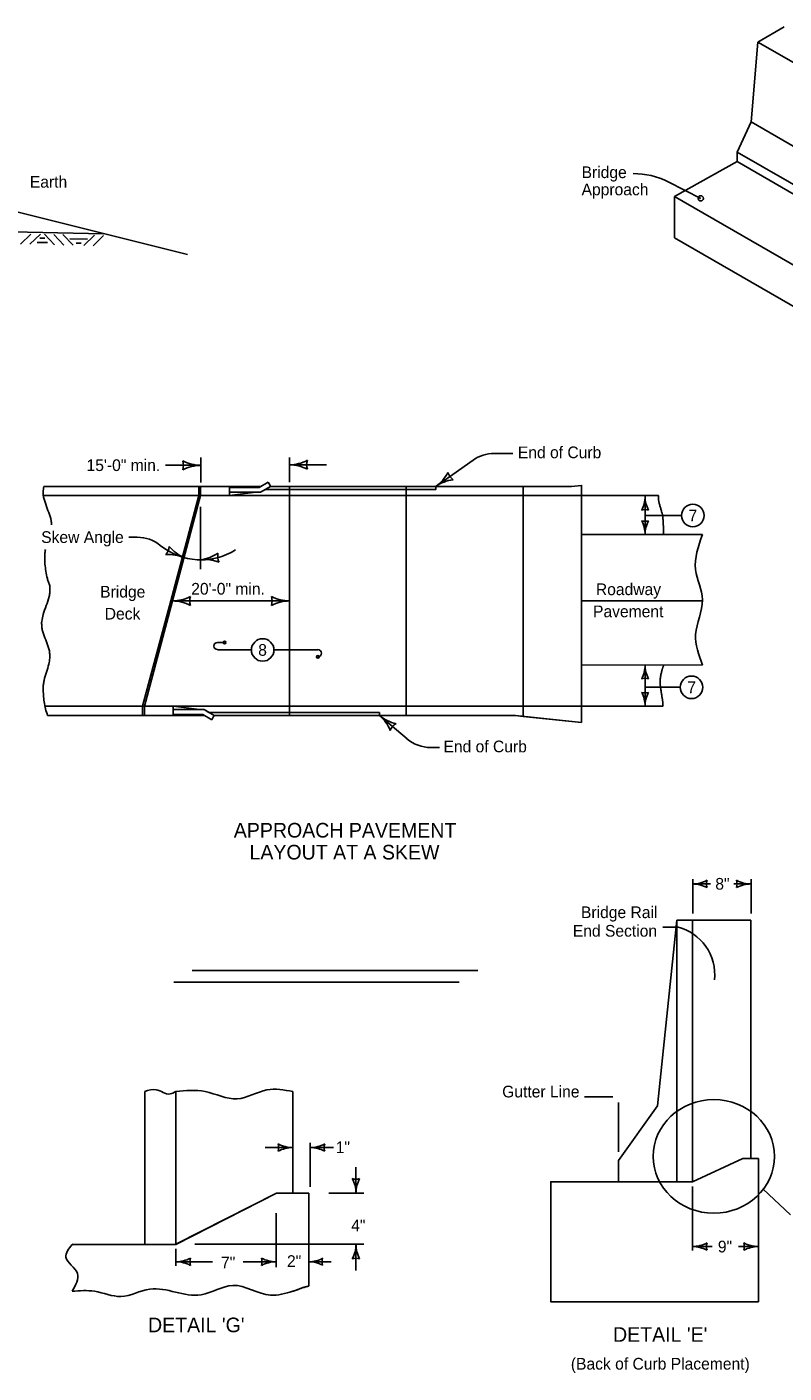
# Model space of a CAD drawing. Extents: x 9234 to 81668, y 5635 to 15999.
# Drawn here: x 18357 to 19394, y 12363 to 14204 of the extents above; entities that cross this region are included whole.
import ezdxf

# ---------------------------------------------------------------- set-up
doc = ezdxf.new("R2010")
doc.units = 0
for name, color, linetype in [('PC_REBAR', 7, 'Continuous'), ('PS_BOLT', 7, 'Continuous'), ('PS_CONST', 7, 'Continuous'), ('PS_DIM', 7, 'Continuous')]:
    doc.layers.add(name, color=color, linetype=linetype)

msp = doc.modelspace()

# ---------------------------------------------------------------- linework, layer by layer
at = {"layer": 'PC_REBAR'}
msp.add_circle((19279.6, 13969.9), 3.54, dxfattribs=at)
at = {"layer": 'PS_CONST'}
for centre in [(18627.7, 13362.4), (18755.4, 13342.7)]:
    msp.add_circle(centre, 1.78, dxfattribs=at)
for centre, radius, start, end in [((19268.2, 13074.5), 42.5, 270, 298.0725), ((19268.2, 12989.5), 42.5, 61.9275, 90), ((19303.8, 13032), 16.4, 162.2666, 197.7334), ((19312.8, 13032), 16.4, 342.2666, 17.7333), ((19348.5, 13074.5), 42.5, 241.9275, 270), ((19348.5, 12989.5), 42.5, 90, 118.0725), ((18685.3, 12671.4), 16.4, 342.2666, 17.7333), ((18721, 12713.9), 42.5, 241.9275, 270), ((18721, 12628.9), 42.5, 90, 118.0725), ((18744.8, 12713.9), 42.5, 270, 298.0725), ((18744.8, 12628.9), 42.5, 61.9275, 90), ((18780.4, 12671.4), 16.4, 162.2666, 197.7334), ((18807.5, 12644.6), 16.4, 252.2666, 287.7333), ((18765, 12609), 42.5, 360, 28.0725), ((18850, 12609), 42.5, 151.9275, 180), ((19268.2, 12578.5), 42.5, 270, 298.0725), ((19303.8, 12536), 16.4, 162.2666, 197.7334), ((19322.8, 12536), 16.4, 342.2666, 17.7333), ((19358.5, 12578.5), 42.5, 241.9275, 270), ((18765, 12539.1), 42.5, 331.9275, 360), ((18850, 12539.1), 42.5, 180, 208.0725), ((19268.2, 12493.5), 42.5, 61.9275, 90), ((19358.5, 12493.5), 42.5, 90, 118.0725), ((18561, 12557.7), 42.5, 270, 298.0725), ((18561, 12472.7), 42.5, 61.9275, 90), ((18596.6, 12515.2), 16.4, 162.2666, 197.7334), ((18662.4, 12515.2), 16.4, 342.2666, 17.7333), ((18698.1, 12557.7), 42.5, 241.9275, 270), ((18698.1, 12472.7), 42.5, 90, 118.0725), ((18807.5, 12503.5), 16.4, 72.2666, 107.7334)]:
    msp.add_arc(centre, radius, start, end, dxfattribs=at)
at = {"layer": 'PS_DIM'}
for p, q in [((19542.8, 14076.9), (19357.8, 14183.7)), ((19533.4, 13967.8), (19348.4, 14074.6)), ((19514.5, 13926.4), (19329.5, 14033.2)), ((19329.5, 14033.2), (19329.5, 14020.1)), ((19234.9, 13992.4), (19258.2, 13980.6)), ((19258.2, 13980.6), (19279.6, 13969.9)), ((18328.6, 13955), (18576.8, 13892.9)), ((18284.3, 13925.1), (18462.2, 13921.5)), ((18362.6, 13920.9), (18348.1, 13907)), ((18375.6, 13920.8), (18361.2, 13907)), ((18381, 13920.7), (18394.8, 13906.3)), ((18394, 13920.3), (18407.8, 13905.8)), ((18406.4, 13920.2), (18420.3, 13905.8)), ((18449.7, 13919.4), (18435.2, 13905.5)), ((18462.1, 13918.9), (18447.7, 13905)), ((18595, 13615.5), (18595, 13581.4)), ((18716.4, 13615.5), (18716.4, 13581.5)), ((18916.9, 13575.8), (18968, 13611.7)), ((18996.7, 13620.8), (19022.5, 13620.8)), ((18595, 13604.7), (18546.6, 13604.7)), ((18767.3, 13605.4), (18716.4, 13605.4)), ((18380.3, 13575.8), (18634.5, 13575.8)), ((18592.6, 13563.2), (18592.6, 13575.8)), ((18594.9, 13563.2), (18594.9, 13575.8)), ((18634.5, 13563.2), (18634.5, 13575.8)), ((18677.2, 13575.8), (18634.5, 13575.8)), ((18674.9, 13574.5), (18687.2, 13581.6)), ((18690.5, 13575.8), (18676.7, 13567.8)), ((18690.5, 13575.8), (18676.7, 13567.8)), ((18683.6, 13571.8), (18916.9, 13571.8)), ((18687.2, 13581.6), (18689.9, 13577)), ((18690.5, 13575.8), (18689.9, 13577)), ((18716.4, 13575.8), (18690.5, 13575.8)), ((18716.4, 13419.2), (18716.4, 13575.8)), ((18716.4, 13575.8), (18876.4, 13575.8)), ((18876.4, 13575.8), (18876.4, 13419.2)), ((18876.4, 13575.8), (19102.5, 13575.8)), ((18916.9, 13575.8), (18916.9, 13571.8)), ((19036.4, 13575.8), (19036.4, 13261.3)), ((19102.5, 13575.8), (19116.4, 13577.3)), ((19116.4, 13577.3), (19116.4, 13419.2)), ((18379.6, 13563.2), (18634.5, 13563.2)), ((18594.9, 13563.2), (18517.8, 13275.2)), ((18592.6, 13563.2), (18554, 13419.2)), ((18594.9, 13563.2), (18556.4, 13419.2)), ((18634.5, 13563.2), (18594.9, 13563.2)), ((18634.5, 13567.8), (18676.7, 13567.8)), ((18634.5, 13563.2), (18670.4, 13567.8)), ((18670.4, 13567.8), (18634.5, 13563.2)), ((19221.6, 13563.2), (18634.5, 13563.2)), ((18676.7, 13567.8), (18670.4, 13567.8)), ((19203.3, 13510), (19203.3, 13563.2)), ((18594.9, 13462.5), (18594.9, 13547.9)), ((19203.3, 13536), (19232.8, 13536)), ((19232.8, 13536), (19253.4, 13536)), ((18496.4, 13506.3), (18508.2, 13506.3)), ((19116.4, 13510), (19281.9, 13510)), ((18515.5, 13275.2), (18554, 13419.2)), ((18517.8, 13275.2), (18556.4, 13419.2)), ((18716.4, 13419.2), (18556.4, 13419.2)), ((18716.4, 13419.2), (18556.4, 13419.2)), ((18716.4, 13419.2), (18716.4, 13262.5)), ((18876.4, 13262.5), (18876.4, 13419.2)), ((19116.4, 13419.2), (19281.9, 13419.2)), ((19116.4, 13419.2), (19116.4, 13252.7)), ((18627.7, 13362.4), (18617.9, 13362.4)), ((18664.4, 13352.5), (18617.9, 13352.5)), ((18695.1, 13352.5), (18755.4, 13352.5)), ((19116.4, 13331.6), (19281.9, 13331.5)), ((19203.3, 13275.2), (19203.3, 13331.6)), ((19203.3, 13301), (19232.8, 13301)), ((19232.8, 13301), (19251.6, 13301)), ((18381.7, 13275.2), (18557.4, 13275.2)), ((18385.3, 13262.5), (18557.4, 13262.5)), ((18515.5, 13262.5), (18515.5, 13275.2)), ((18517.8, 13262.5), (18517.8, 13275.2)), ((18557.4, 13275.2), (18517.8, 13275.2)), ((18557.4, 13275.2), (18557.4, 13262.5)), ((18557.4, 13275.2), (18593.2, 13270.5)), ((18593.2, 13270.5), (18557.4, 13275.2)), ((19227.9, 13275.2), (18557.4, 13275.2)), ((18557.4, 13270.5), (18599.5, 13270.5)), ((18600, 13262.5), (18557.4, 13262.5)), ((18599.5, 13270.5), (18593.2, 13270.5)), ((18597.7, 13263.8), (18610, 13256.7)), ((18606.4, 13266.5), (18599.5, 13270.5)), ((18613.4, 13262.5), (18599.5, 13270.5)), ((18606.4, 13266.5), (18839.7, 13266.5)), ((18610, 13256.7), (18612.7, 13261.3)), ((18613.4, 13262.5), (18612.7, 13261.3)), ((18716.4, 13262.5), (18613.4, 13262.5)), ((18716.4, 13262.5), (18876.4, 13262.5)), ((18839.7, 13262.5), (18839.7, 13266.5)), ((18839.7, 13262.5), (18877.4, 13230.5)), ((19026, 13262.4), (18876.4, 13262.5)), ((19116.4, 13252.7), (19026, 13262.4)), ((18922, 13218.7), (18909.7, 13218.7)), ((19268.5, 12991.4), (19268.5, 13038.7)), ((19348.5, 12991.4), (19348.5, 13038.7)), ((19268.2, 13032), (19292.9, 13032)), ((19324.8, 13032), (19348.5, 13032)), ((19220.2, 12728.3), (19246.9, 12982.3)), ((19246.9, 12982.3), (19348.2, 12982.3)), ((19246.9, 12982.3), (19246.9, 12624.7)), ((19268.2, 12982.3), (19268.2, 12624.7)), ((19348.2, 12982.3), (19348.2, 12656.3)), ((19247.2, 12973.1), (19227.7, 12973.1)), ((18583.3, 12913.6), (18974.2, 12913.6)), ((18558, 12897.6), (18948.9, 12897.6)), ((18518.3, 12748.1), (18518.3, 12539.1)), ((18561, 12748.1), (18561, 12539.1)), ((18721, 12748.1), (18721, 12609)), ((19120.4, 12740.7), (19159.3, 12740.7)), ((19166.8, 12665.4), (19166.8, 12733.2)), ((19166.8, 12653.7), (19220.2, 12728.3)), ((19348.2, 12687.9), (19348.2, 12656.3)), ((18683.3, 12671.4), (18721, 12671.4)), ((18744.8, 12677.8), (18744.8, 12617.8)), ((18744.8, 12671.4), (18777, 12671.4)), ((18721, 12665.5), (18721, 12609)), ((19166.8, 12624.7), (19166.8, 12653.7)), ((19268.2, 12624.7), (19337.3, 12656.3)), ((19358.5, 12656.3), (19337.3, 12656.3)), ((19337.3, 12656.3), (19358.5, 12656.3)), ((19358.5, 12460.5), (19358.5, 12656.3)), ((19358.5, 12656.3), (19358.5, 12460.5)), ((18807.5, 12644.7), (18807.5, 12609)), ((19268.2, 12530.8), (19268.2, 12618.2)), ((19365.1, 12614.3), (19402.3, 12579.4)), ((18742.9, 12609), (18698.7, 12609)), ((18742.9, 12481.7), (18742.9, 12609)), ((18770.4, 12609), (18818.2, 12609)), ((18698.1, 12581.7), (18698.1, 12507.8)), ((18559.8, 12539.1), (18418.8, 12539)), ((18443.1, 12539), (18418.8, 12539)), ((18419, 12539.1), (18465, 12539)), ((18465, 12539), (18443.1, 12539)), ((18560.9, 12539), (18465, 12539)), ((18465, 12539), (18560.9, 12539)), ((18561, 12539.1), (18559.8, 12539.1)), ((18560.9, 12532.7), (18560.9, 12509.7)), ((18586.8, 12539.1), (18818.2, 12539.1)), ((18807.5, 12539.1), (18807.5, 12503.4)), ((19268.2, 12536), (19295.3, 12536)), ((19331.1, 12536), (19358.5, 12536)), ((18561, 12515.2), (18611.1, 12515.2)), ((18653.2, 12515.2), (18698.1, 12515.2)), ((18743, 12515.2), (18773.4, 12515.2))]:
    msp.add_line(p, q, dxfattribs=at)
for points in [[(19357.8, 14183.7), (19393.7, 14204.4)], [(19329.5, 14033.2), (19348.4, 14074.6), (19357.8, 14183.7)], [(19329.5, 14020.1), (19243.7, 13972.5)], [(19514.5, 13913.3), (19329.5, 14020.1)], [(19243.7, 13915.9), (19243.7, 13972.5)], [(19243.7, 13972.5), (19428.7, 13865.7)], [(18371, 13909.6), (18385.1, 13909.3)], [(18374.9, 13915.4), (18381.4, 13915.2)], [(18415.9, 13914.6), (18440, 13914.1)], [(18424.6, 13908.6), (18431.1, 13908.5)], [(19428.7, 13809.1), (19243.7, 13915.9)], [(18674.9, 13574.5), (18634.5, 13574.5), (18634.5, 13574.5), (18634.5, 13574.5)], [(18597.7, 13263.8), (18557.4, 13263.8), (18557.4, 13263.8), (18557.4, 13263.8)], [(19268.2, 12624.7), (19337.3, 12656.3)], [(19358.5, 12460.5), (19074.1, 12460.5), (19074.1, 12624.7), (19220.2, 12624.7), (19268.2, 12624.7)], [(19358.5, 12460.5), (19074.1, 12460.5), (19074.1, 12624.7), (19220.2, 12624.7), (19268.2, 12624.7)], [(18698.7, 12609), (18561, 12539.1), (18560.9, 12539)], [(18560.9, 12539), (18698.7, 12609)], [(18742.9, 12609), (18721, 12609), (18698.7, 12609)], [(18742.9, 12481.7), (18742.9, 12481.7), (18742.9, 12609)]]:
    msp.add_lwpolyline(points, dxfattribs=at)
for points in [[(18594.9, 13563.2), (18634.5, 13563.2), (18670.4, 13567.8), (18676.7, 13567.8), (18676.7, 13567.8), (18676.7, 13567.8), (18682, 13570.9), (18683.6, 13571.8), (18716.4, 13571.8), (18716.4, 13266.5), (18606.4, 13266.5), (18606.2, 13266.6), (18599.5, 13270.5), (18593.2, 13270.5), (18557.4, 13275.2), (18517.8, 13275.2)], [(18690.5, 13575.8), (18683.6, 13571.8), (18916.9, 13571.8), (18916.9, 13575.8)], [(18716.4, 13266.5), (18716.4, 13571.8), (18876.4, 13571.8), (18876.4, 13262.5), (18839.7, 13262.5), (18839.7, 13266.5)], [(18876.4, 13571.8), (18916.9, 13571.8), (18916.9, 13575.8), (19036.4, 13575.8), (19036.4, 13261.3), (19026, 13262.4), (18876.4, 13262.5)], [(19116.4, 13252.7), (19036.4, 13261.3), (19036.4, 13575.8), (19102.5, 13575.8), (19116.4, 13577.3)], [(18606.4, 13266.5), (18613.4, 13262.5), (18839.7, 13262.5), (18839.7, 13266.5)]]:
    msp.add_lwpolyline(points, close=True, dxfattribs=at)
for centre, radius in [((19268.7, 13536), 15.4), ((18627.7, 13362.4), 1.78), ((18679.8, 13352.1), 15.4), ((18679.8, 13352.1), 15.4), ((18755.4, 13342.7), 1.78), ((19267, 13301), 15.4)]:
    msp.add_circle(centre, radius, dxfattribs=at)
for centre, radius, start, end in [((19187.2, 13897.9), 105.9, 63.2177, 90), ((18551.2, 13604.7), 20.2, 342.2667, 17.7334), ((18595, 13656.9), 52.2, 241.9275, 270), ((18716.4, 13657.6), 52.2, 270, 298.0725), ((18760.2, 13605.4), 20.2, 162.2666, 197.7334), ((18996.7, 13570.8), 50, 90, 125.0618), ((18595, 13552.4), 52.2, 90, 118.0725), ((18716.4, 13553.2), 52.2, 61.9275, 90), ((18886.9, 13618.6), 52.2, 305.0618, 333.1343), ((18952.7, 13601), 20.2, 197.3284, 232.7951), ((18946.9, 13533.1), 52.2, 96.9893, 125.0618), ((19163.2, 13562.3), 40.2, 331.9275, 360), ((19243.5, 13562.3), 40.2, 180, 208.0725), ((19203.3, 13528.6), 15.5, 72.2666, 107.7334), ((19203.3, 13543.7), 15.5, 252.2666, 287.7333), ((19163.2, 13510), 40.2, 360, 28.0725), ((19243.5, 13510), 40.2, 151.9275, 180), ((18508.2, 13456.3), 50, 51.0377, 90), ((18595.4, 13564.1), 88.7, 231.0377, 302.325), ((18531.8, 13495.3), 20.2, 319.762, 355.2287), ((18552.3, 13430.3), 52.2, 67.4953, 95.5678), ((18592.3, 13526.8), 52.2, 219.4229, 247.4953), ((18588.7, 13527.3), 52.2, 276.8099, 304.8824), ((18588.7, 13527.3), 52.2, 276.8099, 304.8823), ((18638.4, 13480.6), 20.2, 169.0765, 204.5432), ((18638.4, 13480.6), 20.2, 169.0765, 204.5432), ((18601.1, 13423.6), 52.2, 68.7374, 96.8099), ((18595.4, 13564.1), 88.7, 269.6725, 274.9601), ((18601.1, 13423.6), 52.2, 68.7374, 87.8227), ((18556.4, 13471.4), 52.2, 270, 298.0725), ((18556.4, 13471.4), 52.2, 270, 298.0725), ((18600.2, 13419.2), 20.2, 162.2666, 197.7334), ((18600.2, 13419.2), 20.2, 162.2667, 197.7333), ((18672.6, 13419.2), 20.2, 342.2667, 17.7334), ((18716.4, 13471.4), 52.2, 241.9275, 270), ((18716.4, 13471.4), 52.2, 241.9275, 270), ((18672.6, 13419.2), 20.2, 342.2667, 17.7333), ((18556.4, 13366.9), 52.2, 61.9275, 90), ((18556.4, 13366.9), 52.2, 61.9275, 90), ((18716.4, 13366.9), 52.2, 90, 118.0725), ((18716.4, 13366.9), 52.2, 90, 118.0725), ((18617.9, 13357.5), 4.92, 90, 270), ((18755.4, 13347.6), 4.92, 270, 90), ((19163.2, 13331.6), 40.2, 331.9275, 360), ((19243.5, 13331.6), 40.2, 180, 208.0725), ((19203.3, 13297.9), 15.5, 72.2666, 107.7334), ((19203.3, 13308.9), 15.5, 252.2666, 287.7333), ((19163.2, 13275.2), 40.2, 360, 28.0725), ((19243.5, 13275.2), 40.2, 151.9275, 180), ((18806, 13222.6), 52.2, 21.6804, 49.7529), ((18873.4, 13302.3), 52.2, 229.7529, 257.8254), ((18873.1, 13234.2), 20.2, 122.0196, 157.4863), ((18909.7, 13268.7), 50, 229.7529, 270), ((19232, 12908.2), 66.7, 353.5756, 76.8823), ((18743, 12555.5), 40.3, 270, 298.0725), ((18743, 12474.9), 40.3, 61.9275, 90), ((18776.8, 12515.2), 15.6, 162.2666, 197.7334)]:
    msp.add_arc(centre, radius, start, end, dxfattribs=at)
msp.add_ellipse((19297.5, 12659.3), major_axis=(83, 0), ratio=0.93542, dxfattribs=at)
for points in [[(18390.7, 13523.3), (18390.7, 13523.6), (18390.2, 13529.2), (18389.9, 13530.6), (18389.7, 13532), (18388.9, 13534.7), (18384.9, 13545.8), (18381, 13556.9), (18379.7, 13562.4), (18379.4, 13565.2), (18379.3, 13568), (18379.6, 13571.9), (18380.3, 13575.8)], [(19281.9, 13510), (19272.5, 13462), (19281.9, 13420.8), (19272.5, 13373.3), (19281.9, 13331.5)], [(18388.2, 13440), (18386.5, 13444.9), (18385.1, 13449.8), (18383, 13459.7), (18381.8, 13469.5), (18381.5, 13474.4), (18381.4, 13479.2), (18381.7, 13484.8), (18382.4, 13489.3)], [(18385.3, 13262.5), (18382.5, 13271.7), (18380.7, 13281), (18379.7, 13290.2), (18379.4, 13294.8), (18379.2, 13299.4), (18379.6, 13305), (18380.6, 13310.5), (18383.8, 13321.6), (18387, 13332.7), (18388.4, 13341), (18388.5, 13342.4), (18388.5, 13343.8), (18388, 13349.3), (18386.7, 13354.9), (18382.8, 13366), (18378.8, 13377), (18377.6, 13382.6), (18377.2, 13388.1), (18377.2, 13389.7), (18377.4, 13391.2), (18379.3, 13400.5), (18383.6, 13412.8), (18387.5, 13425.2), (18388.5, 13431.4), (18388.5, 13437.7), (18388.2, 13440)], [(18518.3, 12748.1), (18534, 12750.6), (18553, 12744.7), (18561, 12748.1)], [(18561, 12748.1), (18601, 12748.1), (18644.8, 12738), (18685.6, 12750.3), (18721, 12748.1)], [(18418.8, 12539), (18410.5, 12521.4), (18426.2, 12499.3), (18419, 12474.8)], [(18418.8, 12539), (18410.5, 12521.4), (18426.2, 12499.3), (18419, 12474.8)], [(18419, 12474.8), (18449.6, 12474.8), (18485.7, 12467.7), (18525.4, 12477.7), (18595.4, 12470.1), (18639.1, 12482.9), (18690.5, 12469.5), (18721, 12474.8)], [(18419, 12474.8), (18449.6, 12474.8), (18485.7, 12467.7), (18525.4, 12477.7), (18595.4, 12470.1), (18639.1, 12482.9), (18690.5, 12469.5), (18721, 12474.8)], [(18721, 12474.8), (18735.1, 12479.8), (18740.3, 12481.4)]]:
    msp.add_spline(points, degree=3, dxfattribs=at)
for points in [[(19221.6, 13563.2), (19221.6, 13563.2), (19221.6, 13563.1), (19221.6, 13563.1), (19221.5, 13562.5), (19221.5, 13561.9), (19221.5, 13561.3), (19221.5, 13560.6), (19221.5, 13560), (19221.6, 13559.4), (19221.6, 13558.3), (19221.8, 13557.2), (19222, 13556), (19222.2, 13554.9), (19222.4, 13553.7), (19222.7, 13552.6), (19223.4, 13550.3), (19224, 13548.1), (19224.7, 13545.8), (19225.4, 13543.5), (19226, 13541.2), (19226.7, 13538.9), (19227, 13537.8), (19227.2, 13536.6), (19227.4, 13535.5), (19227.6, 13534.3), (19227.7, 13533.1), (19227.8, 13532), (19227.9, 13530.1), (19228, 13528.3), (19228.1, 13526.5), (19228.2, 13524.7), (19228.3, 13522.8), (19228.4, 13521), (19228.5, 13519.2), (19228.6, 13517.4), (19228.6, 13515.5), (19228.7, 13513.7), (19228.8, 13511.9), (19228.8, 13510.1)], [(19228.8, 13331.6), (19228.4, 13330.5), (19228.1, 13329.5), (19227.7, 13328.4), (19227.4, 13327.3), (19227.1, 13326.3), (19226.7, 13325.2), (19226.1, 13323.1), (19225.6, 13321), (19225.1, 13318.8), (19224.5, 13315.6), (19224.1, 13312.4), (19224, 13309.2), (19224, 13308.7), (19224, 13308.1), (19224, 13307.6), (19224, 13307.1), (19224, 13306.5), (19224.1, 13306), (19224.1, 13304.8), (19224.2, 13303.6), (19224.4, 13302.4), (19224.5, 13301.2), (19224.6, 13300), (19224.8, 13298.8), (19225.2, 13296.4), (19225.6, 13294), (19225.9, 13291.6), (19226.3, 13289.3), (19226.7, 13286.9), (19227.1, 13284.5), (19227.3, 13283.3), (19227.4, 13282.1), (19227.5, 13280.9), (19227.6, 13279.7), (19227.7, 13278.5), (19227.8, 13277.3), (19227.8, 13276.6), (19227.9, 13275.9), (19227.9, 13275.2)], [(18721, 12474.8), (18721.9, 12475), (18722.8, 12475.3), (18723.7, 12475.6), (18724.6, 12476), (18725.5, 12476.3), (18726.5, 12476.6), (18728.3, 12477.3), (18730.1, 12478.1), (18732, 12478.8), (18733.8, 12479.5), (18735.6, 12480.1), (18737.5, 12480.7), (18738.4, 12480.9), (18739.3, 12481.1), (18740.2, 12481.3), (18740.6, 12481.4), (18741.1, 12481.5), (18741.6, 12481.6), (18742, 12481.6), (18742.5, 12481.7), (18742.9, 12481.7)]]:
    msp.add_open_spline(points, degree=3, dxfattribs=at)

# ---------------------------------------------------------------- texts
at = {"layer": 'PS_BOLT'}
for s, p in [('End of Curb', (19029.2, 13614.4)), ('15\'-0" min.', (18438.7, 13596.9)), ('7', (19262.9, 13528)), ('Skew Angle', (18376.6, 13498.5)), ('20\'-0" min.', (18582, 13427.8)), ('Roadway', (19136, 13427.1)), ('Bridge', (18457.3, 13423.8)), ('Deck', (18463.6, 13393.7)), ('Pavement', (19132.1, 13396.9)), ('8', (18673.7, 13344.1)), ('7', (19261.1, 13293)), ('End of Curb', (18927.3, 13212.1)), ('(Back of Curb Placement)', (19101.7, 12367.7))]:
    msp.add_text(s, height=16, dxfattribs=at).set_placement(p)
at = {"layer": 'PS_CONST'}
for s, height, p in [('Earth', 16, (18361.1, 13984.5)), ('APPROACH PAVEMENT', 20, (18640.3, 13095.5)), ('LAYOUT AT A SKEW', 20, (18661.8, 13065.5))]:
    msp.add_text(s, height=height, dxfattribs=at).set_placement(p)
at = {"layer": 'PS_DIM'}
for s, height, p in [('Bridge', 16, (19116.4, 13997.6)), ('Approach', 16, (19116.4, 13974.1)), ('8"', 16, (19299.5, 13024.2)), ('Bridge Rail ', 16, (19115.6, 12985.3)), ('End Section', 16, (19104.4, 12959.9)), ('Gutter Line', 16, (19007.7, 12740)), ('1"', 16, (18779.8, 12663.8)), ('4"', 16, (18801, 12556.9)), ('9"', 16, (19303, 12528)), ('7"', 16, (18622.8, 12506.1)), ('2"', 16, (18713.1, 12508.1)), ("DETAIL 'G'", 20, (18522.9, 12418.8)), ("DETAIL 'E'", 20, (19159.5, 12405.7))]:
    msp.add_text(s, height=height, dxfattribs=at).set_placement(p)

doc.saveas('drawing.dxf')
